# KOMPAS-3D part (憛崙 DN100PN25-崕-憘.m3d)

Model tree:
1. Объединить компоненты:1  (labels: СЕНС DN100PN25-НО)
2. Эскиз:1
3. Операция выдавливания:1
     Расстояние 1 = 14
4. Фаска:1
     Угол = 45; Длина 1 = 2; Длина 2 = 2

Referenced files in D:\Савин\!СЕНСОР\3D для заказчика\!Новый перечень\СЕНС\2. СЕНС-НО\DN100\: СЕНС DN100PN25-НО.a3d
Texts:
  СЕНС DN100PN25-НО-СВ
  ООО НПП Сенсор
  СЕНС DN100PN25-НО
